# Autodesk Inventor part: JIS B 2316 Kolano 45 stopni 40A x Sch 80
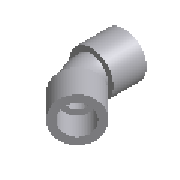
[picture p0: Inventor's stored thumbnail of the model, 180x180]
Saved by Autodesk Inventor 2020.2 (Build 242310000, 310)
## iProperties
Manager: www.cadconsulting.pl
Company: Fabian Stasiak CAD Consulting
NAME: PIPING: JIS B 2316 45 Deg Elbow
DATA: <meta><inlinegroups number="0" deflen="0"></inlinegroups><connections number="2"></connections><angles><a>2.35619449019234</a></angles></meta>
IsCustomPart: 0
Created: 2014-02
Part Number: JIS B 2316 Kolano 45 stopni 40A x Sch 80
Material: Stal
Description: Kolano
Document SubType Name: Modeling
Standard: JIS B 2316
Designer: F.Stasiak
Standards Organization: JIS
Language: pl-PL
Size Designation: 40A x Sch 80
Categories: <MemberInstance><Categories><Category DisplayName="Rury cienko- i grubościenne" InternalName="4347fa0f-2144-441d-94cd-e3e15c92b736" Mnemonic="TUBEANDPIPE"><Cate
Density: 1 g/cm^3
Appearance: Płyta
Catalog Web Link: www.expertbooks.pl
Author: F.Stasiak
Subject: Zbiór ćwiczeń. Autodesk Inventor 2020. Kurs Professional
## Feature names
1. Revolve1
2. Revolve2
3. Sweep1
## Parameters: S = 49.1 mm, D = 41.2 mm, T = 5.6 mm, C1 = 12.7 mm, G = 20.6 mm, d0 = 41.2 mm, d1 = 49.1 mm, d2 = 5.6 mm, d3 = 12.7 mm, d8 = 90 deg, d4 = 41.2 mm, d5 = 49.1 mm, d6 = 5.6 mm, d7 = 12.7 mm, d25 = 90 deg, d9 = 45 deg, d10 = 20.6 mm, d11 = 20.6 mm, d12 = 52.4 mm, d13 = 0, d37 = 0, Size_Designation = 12.345 mm
